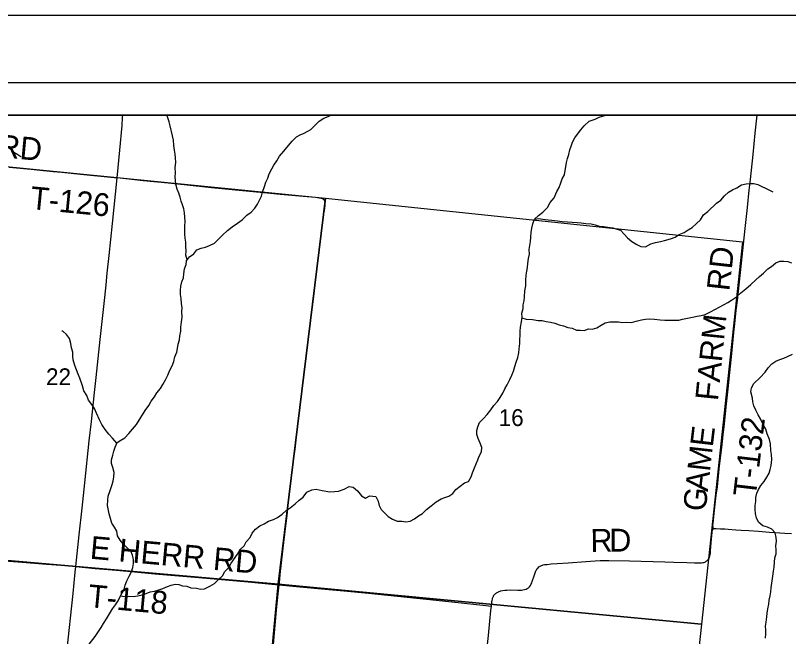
# Model space of a CAD drawing. Extents: x 0 to 1067, y 0 to 440.
# Drawn here: x 393.3 to 508.9, y 347.2 to 440 of the extents above; entities that cross this region are included whole.
import ezdxf

# ---------------------------------------------------------------- set-up
doc = ezdxf.new("R2010")
doc.units = 0
for name, color, linetype in [('GM_X_County_Road', 7, 'Continuous'), ('GM_X_County_Road_Text', 7, 'Continuous'), ('GM_X_Minor_River', 7, 'Continuous'), ('GM_X_Section', 7, 'Continuous'), ('GM_X_Section_Text', 7, 'Continuous'), ('GM_X_Township_Road', 7, 'Continuous'), ('GM_X_Township_Road_Text', 7, 'Continuous'), ('GM_X_US_Route', 7, 'Continuous'), ('SH_Border', 7, 'Continuous'), ('SH_Cut_Line', 7, 'Continuous'), ('SH_Text', 7, 'Continuous')]:
    doc.layers.add(name, color=color, linetype=linetype)

msp = doc.modelspace()

# ---------------------------------------------------------------- linework, layer by layer
at = {"layer": 'GM_X_County_Road'}
for points in [[(464.46, 351.72), (464.48, 351.95), (464.51, 352.18), (464.54, 352.41), (464.57, 352.57), (464.6, 352.73), (464.63, 352.88), (464.67, 353.01), (464.71, 353.09), (464.75, 353.17), (464.79, 353.24), (464.84, 353.33), (464.89, 353.4), (464.95, 353.47), (465.02, 353.54), (465.07, 353.59), (465.15, 353.65), (465.22, 353.7), (465.31, 353.76), (465.41, 353.81), (465.5, 353.86), (465.6, 353.9), (465.76, 353.96), (465.88, 353.99), (466.13, 354.05), (466.46, 354.09), (466.79, 354.11), (467.38, 354.12), (468.39, 354.11), (468.74, 354.11), (468.97, 354.11), (469.18, 354.13), (469.43, 354.18), (469.64, 354.25), (469.83, 354.33), (470.01, 354.45), (470.16, 354.6), (470.29, 354.79), (470.43, 355.03), (470.5, 355.19), (470.58, 355.38), (470.91, 356.38), (471.07, 356.83), (471.18, 357.06), (471.24, 357.2), (471.32, 357.31), (471.44, 357.45), (471.58, 357.58), (471.75, 357.69), (471.93, 357.78), (472.08, 357.84), (472.2, 357.87), (472.39, 357.91), (472.57, 357.93), (472.78, 357.95), (473.42, 358.01), (474.32, 358.07), (475.95, 358.19), (478.59, 358.38), (479.97, 358.48), (480.75, 358.52), (481.19, 358.53), (482.01, 358.53), (485.11, 358.47), (490.43, 358.35), (491.74, 358.3), (493.71, 358.23), (494.83, 358.18), (495.52, 358.16), (495.74, 358.16), (495.9, 358.18), (496.08, 358.21), (496.23, 358.23), (496.37, 358.27), (496.48, 358.32), (496.61, 358.41), (496.71, 358.49), (496.81, 358.59), (496.92, 358.73), (497.02, 358.88), (497.07, 359), (497.13, 359.17), (497.17, 359.36), (497.2, 359.5), (497.22, 359.62), (497.23, 359.79), (497.25, 359.96), (497.34, 361.24), (497.47, 362.74), (497.48, 362.85), (497.5, 362.96), (497.52, 363.03), (497.54, 363.09), (497.56, 363.13), (497.58, 363.17), (497.61, 363.21), (497.65, 363.24), (497.71, 363.27)], [(497.71, 363.27), (497.78, 363.3), (497.85, 363.31), (497.92, 363.31), (497.99, 363.31), (498.08, 363.31), (498.71, 363.28), (499.38, 363.25), (499.9, 363.21), (501.02, 363.12), (501.83, 363.06), (502.95, 362.99), (504.4, 362.89), (506.07, 362.78), (508.34, 362.62), (509.38, 362.55)], [(461.03, 321.28), (461.15, 321.95), (461.26, 322.66), (461.36, 323.36), (461.47, 324.28), (461.62, 325.62), (461.76, 326.9), (461.92, 328.34), (462.05, 329.49), (462.18, 330.74), (462.27, 331.57), (462.5, 333.82), (462.8, 336.66), (463.06, 338.89), (463.26, 340.5), (463.48, 342.36), (463.92, 346.42), (464.01, 347.3), (464.24, 349.44), (464.39, 351.07), (464.46, 351.72)]]:
    msp.add_lwpolyline(points, dxfattribs=at)
at = {"layer": 'GM_X_Minor_River'}
for points in [[(385.01, 424.77), (385.45, 424.18), (386.11, 424.09), (386.68, 424.08), (387.3, 423.64), (387.81, 422.96), (388.24, 422.39), (388.88, 421.86), (389.45, 421.6), (390.06, 421.26), (390.65, 420.96), (391.22, 420.72), (391.81, 420.49), (392.4, 420.14), (392.99, 419.55), (393.63, 419.2), (394.04, 418.93)], [(408.01, 371.69), (407.84, 372.45), (407.61, 373.02), (407.64, 373.59), (407.81, 374.27), (407.99, 374.88), (408.18, 375.47), (408.46, 376.18), (409.04, 376.52), (409.61, 376.87), (410.23, 377.51), (410.79, 378.16), (411.34, 378.86), (412.67, 380.97), (413.2, 381.72), (413.57, 382.37), (414.08, 383.01), (414.43, 383.6), (414.93, 384.25), (415.31, 384.86), (415.7, 385.52), (416.03, 386.25), (416.35, 386.99), (416.7, 387.65), (416.96, 388.29), (417.12, 388.95), (417.41, 389.65), (417.52, 390.24), (417.62, 390.88), (417.79, 391.53), (417.84, 392.13), (417.98, 392.81), (418.01, 393.4), (418.11, 394.22), (418.18, 394.9), (418.17, 395.74), (418.18, 396.31), (418.11, 396.97), (418.05, 397.7), (417.97, 398.29), (417.97, 398.93), (418.02, 399.54), (418.14, 400.2), (418.4, 400.79), (418.43, 401.36), (418.57, 402.11), (418.78, 402.76), (418.86, 403.33), (419.3, 403.92), (419.92, 404.37), (420.4, 404.98), (421.02, 405.24), (421.69, 405.37), (422.28, 405.62), (423.02, 405.97), (423.64, 406.54), (424.24, 407.15), (424.98, 407.87), (425.67, 408.4), (426.47, 408.94), (427.16, 409.46), (427.88, 410.13), (428.52, 410.6), (429.07, 411.19), (429.47, 411.78), (429.77, 412.39), (430.05, 412.98), (430.19, 413.57), (430.5, 414.43), (430.69, 415.08), (431.01, 415.69), (431.22, 416.35), (431.62, 417.07), (431.92, 417.64), (432.34, 418.29), (432.78, 418.99), (433.4, 419.71), (434.1, 420.55), (434.67, 421.2), (435.3, 421.85), (435.87, 422.14), (436.47, 422.41), (437.45, 422.97), (438.12, 423.67), (438.7, 424.21), (439.41, 424.63), (440.03, 424.92), (440.46, 425.11)], [(418.95, 403.45), (418.73, 404.17), (418.78, 404.79), (418.76, 405.52), (418.72, 406.13), (418.66, 406.7), (418.6, 407.31), (418.6, 407.9), (418.59, 408.49), (418.64, 409.18), (418.58, 409.86), (418.54, 410.49), (418.47, 411.09), (418.27, 411.68), (418.07, 412.25), (417.9, 412.84), (417.7, 413.46), (417.45, 414.03), (417.27, 414.8), (417.13, 415.87), (417.2, 416.48), (417.14, 417.28), (417.26, 418), (417.2, 418.71), (417.13, 419.28), (417.07, 419.89), (416.96, 420.57), (416.88, 421.37), (416.73, 422.03), (416.4, 423.51), (416.27, 424.12), (416.07, 424.71), (415.91, 425.11)], [(464.36, 381.06), (464.8, 381.69), (465.38, 382.3), (465.75, 382.87), (466.17, 383.53), (466.45, 384.21), (466.84, 384.77), (467.24, 385.59), (467.54, 386.25), (467.75, 386.81), (467.96, 387.52), (468.18, 388.18), (468.39, 388.86), (468.55, 389.56), (468.63, 390.15), (468.7, 390.97), (468.71, 391.54), (468.76, 392.15), (468.77, 392.79), (468.79, 393.41), (468.94, 394.2), (469.04, 394.88), (469.02, 395.5), (469.23, 396.18), (469.21, 396.77), (469.36, 397.36), (469.41, 397.95), (469.44, 398.84), (469.61, 399.59), (469.59, 400.36), (469.64, 401.2), (469.76, 401.77), (469.86, 402.34), (469.91, 402.91), (469.99, 403.68), (470.15, 404.34), (470.09, 405), (470.19, 405.61), (470.33, 406.22), (470.36, 406.84), (470.39, 407.56), (470.51, 408.22), (470.67, 408.86), (470.91, 409.54), (471.53, 410.12), (472.13, 410.62), (472.87, 411.29), (473.26, 412.02), (473.84, 412.72), (474.24, 413.71), (474.59, 414.28), (474.84, 414.96), (475.06, 415.59), (475.4, 416.2), (475.48, 416.82), (475.57, 417.38), (475.69, 418.02), (475.86, 418.61), (476.05, 419.22), (476.19, 419.9), (476.38, 420.47), (476.57, 421.06), (476.96, 421.71), (477.33, 422.28), (477.82, 422.91), (478.35, 423.52), (479.07, 424.19), (479.96, 424.5), (480.56, 424.79), (481.6, 425.11)], [(470.94, 409.57), (471.57, 409.65), (472.17, 409.57), (472.94, 409.47), (473.51, 409.38), (474.33, 409.28), (475.06, 409.22), (475.84, 409.17), (476.53, 409.1), (477.28, 409.04), (477.89, 409.02), (478.58, 408.92), (479.36, 408.86), (479.97, 408.68), (480.56, 408.53), (481.25, 408.44), (481.89, 408.34), (482.62, 408.26), (483.21, 408.08), (483.78, 407.91), (484.3, 407.32), (484.84, 406.74), (485.45, 406.21), (486.2, 405.75), (486.82, 405.47), (487.52, 405.4), (488.31, 405.84), (489.02, 406.04), (489.75, 406.22), (490.34, 406.35), (491.24, 406.61), (491.97, 406.88), (492.54, 407.28), (493.28, 407.57), (493.88, 407.97), (494.5, 408.31), (495.16, 408.92), (495.74, 409.43), (496.2, 410.18), (496.83, 410.7), (498.12, 411.96), (498.76, 412.38), (499.31, 413.02), (499.94, 413.6), (500.53, 413.94), (501.18, 414.23), (501.89, 414.7), (502.58, 414.85), (503.15, 414.87), (503.74, 414.88), (504.31, 414.72), (504.9, 414.44), (505.47, 414.21), (506.08, 413.88), (506.54, 413.65)], [(469.02, 394.79), (469.65, 394.58), (470.59, 394.53), (471.48, 394.38), (472.07, 394.4), (472.66, 394.23), (473.28, 394.14), (473.94, 393.99), (474.58, 393.78), (475.24, 393.59), (475.88, 393.36), (476.54, 393.28), (477.17, 392.98), (477.75, 392.98), (478.36, 392.92), (478.98, 393.15), (479.55, 393.09), (480.22, 393.29), (480.86, 393.72), (481.48, 394.05), (482.17, 394.21), (482.83, 394.22), (483.49, 394.22), (484.06, 394.12), (484.7, 394.16), (485.41, 394.11), (486.12, 394.28), (486.92, 394.48), (487.49, 394.61), (488.11, 394.65), (488.86, 394.6), (489.71, 394.5), (490.42, 394.44), (491.76, 394.43), (492.49, 394.45), (493.07, 394.58), (493.8, 394.77), (494.55, 394.88), (495.22, 395.03), (495.84, 395.14), (496.43, 395.32), (497.26, 395.72), (497.97, 396.12), (498.54, 396.41), (499.26, 396.81), (499.83, 397.11), (500.4, 397.42), (501.12, 397.96), (501.78, 398.54), (502.52, 399.15), (503.26, 399.78), (503.99, 400.43), (504.59, 400.97), (505.17, 401.47), (505.79, 402.12), (506.37, 402.46), (507.01, 403), (507.61, 403.29), (508.22, 403.26), (508.79, 403.23), (509.36, 403)], [(408.43, 376.09), (407.78, 376.8), (407.24, 377.42), (406.7, 378.13), (406.18, 378.87), (405.84, 379.55), (405.37, 380.56), (405.06, 381.27), (404.7, 381.84), (404.2, 382.51), (403.94, 383.2), (403.49, 383.91), (403.31, 384.66), (402.89, 385.78), (402.66, 386.37), (402.37, 387.04), (402.15, 387.68), (401.88, 388.5), (401.84, 389.09), (401.85, 389.68), (401.65, 390.34), (401.54, 390.96), (401.34, 391.69), (400.91, 392.29), (400.32, 392.79), (400.21, 392.82)], [(505.88, 387.32), (506.41, 387.93), (507.01, 388.31), (507.63, 388.56), (508.2, 388.76), (508.78, 389.02), (509.51, 389.38)], [(505.47, 346.94), (505.54, 347.55), (505.53, 348.12), (505.46, 348.7), (505.56, 349.33), (505.66, 350.09), (505.71, 350.66), (505.81, 351.29), (505.95, 352), (506.02, 352.59), (506.14, 353.23), (506.24, 353.85), (506.31, 354.46), (506.41, 355.14), (506.54, 356.19), (506.66, 356.92), (506.75, 357.54), (506.81, 358.27), (506.88, 358.93), (507.07, 359.54), (507.05, 360.14), (506.99, 360.73), (507.09, 361.41), (507.05, 361.98), (506.89, 362.65), (506.39, 363.22), (505.78, 363.5), (505.07, 363.71), (504.48, 364.2), (504.1, 364.84), (503.97, 365.53), (503.91, 366.14), (503.94, 366.74), (504.01, 367.33), (504.04, 367.97), (504.18, 368.58), (504.44, 369.15), (504.76, 369.74), (505.25, 370.35), (505.69, 371.01), (505.99, 371.57), (506.18, 372.14), (506.32, 372.71), (506.42, 373.64), (506.38, 374.35), (506.25, 374.99), (506.21, 375.97), (506.08, 376.61), (505.72, 377.48), (505.53, 378.17), (505.17, 378.78), (504.74, 379.72), (504.38, 380.3), (504.02, 380.98), (503.73, 381.65), (503.55, 382.24), (503.51, 382.81), (503.29, 383.75), (503.37, 384.34), (503.71, 384.97), (504.66, 385.88), (505.44, 386.69), (505.88, 387.32)], [(408.94, 353.23), (409.6, 353.17), (410.22, 353.21), (410.88, 353.16), (411.57, 353.24), (412.19, 353.42), (412.8, 353.62), (413.42, 353.84), (414.04, 353.95), (414.73, 354.13), (415.32, 354.35), (415.99, 354.64), (416.56, 354.82), (417.13, 354.97), (417.71, 354.94), (418.27, 354.73), (418.87, 354.68), (419.51, 354.45), (420.33, 354.37), (420.92, 354.23), (421.56, 354.27), (422.34, 354.69), (423.03, 355.07), (423.63, 355.71), (424.23, 356.25), (424.58, 356.86), (425.15, 357.45), (425.55, 358.13), (426.47, 359.49), (426.89, 360.17), (427.49, 360.74), (427.77, 361.33), (428.35, 361.98), (428.69, 362.6), (429.18, 363.21), (429.8, 363.7), (430.44, 364.02), (431.11, 364.4), (431.87, 364.64), (432.48, 364.96), (433.17, 365.45), (433.77, 365.99), (434.35, 366.38), (435.11, 366.98), (435.71, 367.53), (436.3, 368.02), (436.86, 368.75), (437.59, 369.1), (438.26, 369.21), (439.15, 369), (440.29, 368.78), (440.97, 368.82), (441.57, 368.88), (442.44, 369.17), (443.2, 369.6), (443.77, 369.5), (444.45, 368.92), (445.01, 368.19), (445.62, 367.86), (446.27, 368.18), (447.18, 368.08), (447.54, 367.39), (447.65, 366.77), (447.98, 366.15), (449.03, 365.12), (449.64, 364.7), (450.34, 364.42), (451.05, 364.39), (451.67, 364.31), (452.31, 364.4), (452.97, 364.78), (453.55, 365.21), (454.17, 365.54), (454.77, 366.15), (455.46, 366.72), (456.22, 367.3), (456.93, 367.73), (457.5, 367.95), (458.1, 368.13), (458.67, 368.53), (459.16, 369.12), (459.78, 369.64), (460.45, 370.16), (461.04, 370.36), (461.42, 371.02), (461.65, 371.63), (461.91, 372.4), (462.19, 372.97), (462.42, 373.56), (462.65, 374.13), (462.98, 374.78), (463.01, 375.4), (462.76, 376.06), (462.47, 376.77), (462.3, 377.34), (462.26, 377.94), (462.42, 378.53), (462.68, 379.16), (463.3, 379.75), (463.83, 380.36), (464.36, 381.06)], [(404.26, 346), (405.19, 347.18), (405.67, 347.93), (406.07, 348.52), (406.44, 349.11), (406.88, 349.79), (407.32, 350.56), (407.76, 351.29), (408.2, 351.88), (408.61, 352.49), (408.85, 353.06), (409.2, 353.68), (409.5, 354.24), (409.66, 354.84), (409.9, 355.5), (410.27, 356.2), (410.62, 356.81), (410.83, 357.5), (410.93, 358.09), (410.91, 358.68), (410.75, 359.32), (410.53, 359.92), (409.94, 360.47), (409.35, 361), (408.92, 361.58), (408.5, 362.24), (408.41, 362.9), (408.07, 363.52), (407.67, 364.1), (407.49, 364.81), (407.29, 365.49), (407.03, 366.77), (407.06, 367.53), (407.13, 368.16), (407.42, 369.01), (407.67, 369.73), (407.89, 370.39), (407.98, 371.03), (408.01, 371.69)]]:
    msp.add_lwpolyline(points, dxfattribs=at)
at = {"layer": 'GM_X_Section'}
for points in [[(377.26, 418.88), (439.65, 412.67), (432.58, 354.98), (371.52, 360.33)], [(502.03, 406.17), (495.9, 348.99), (432.58, 354.98), (439.65, 412.67)], [(432.58, 354.98), (426.84, 293.81), (365.53, 299.9), (371.52, 360.33)], [(432.58, 354.98), (495.9, 348.99), (489.23, 287.4), (426.84, 293.81)]]:
    msp.add_lwpolyline(points, close=True, dxfattribs=at)
at = {"layer": 'GM_X_Township_Road'}
for points in [[(539, 425.11), (252.4, 425.11), (247.73, 377.87), (241.1, 310.88), (230.69, 191.54)], [(497.71, 363.27), (497.68, 363.33), (497.65, 363.41), (497.62, 363.49), (497.62, 363.55), (497.61, 363.62), (497.61, 363.82), (497.63, 364.08), (497.8, 365.59), (498.11, 368.29), (498.26, 369.55), (498.55, 372.22), (498.91, 375.4), (499.14, 377.33), (499.31, 378.96), (499.58, 381.52), (499.91, 384.63), (500.11, 386.61), (500.41, 389.46), (500.75, 392.6), (500.88, 393.93), (501.1, 395.97), (501.26, 397.38), (501.87, 402.97), (502.18, 405.83), (502.43, 408.16), (502.76, 411.31), (503.03, 413.91), (503.21, 415.5), (503.61, 419.21), (503.94, 422.4), (504.24, 425.11)], [(408.48, 415.71), (408, 415.75), (402.99, 416.25), (400.17, 416.52), (398.91, 416.65), (395.56, 416.96), (392.33, 417.26)], [(432.71, 354.9), (432.74, 355.19), (432.86, 356.42), (433, 357.75), (433.32, 360.38), (433.57, 362.49), (433.88, 365.27), (434.06, 366.79), (434.36, 369.49), (434.77, 372.78), (435.08, 375.19), (435.47, 378.33), (435.8, 381.07), (436.06, 383.18), (436.35, 385.55), (436.51, 386.8), (436.66, 388.14), (436.9, 390.27), (437.05, 391.58), (437.32, 393.55), (437.49, 394.91), (437.89, 397.98), (438.1, 399.67), (438.36, 401.92), (438.56, 403.59), (438.74, 404.99), (438.95, 406.63), (439.14, 408.5), (439.24, 409.29), (439.35, 410.06), (439.52, 411.14), (439.59, 411.68), (439.6, 411.8), (439.61, 411.89), (439.61, 411.97), (439.6, 412.04), (439.6, 412.11), (439.58, 412.17), (439.56, 412.21), (439.54, 412.26), (439.5, 412.32), (439.46, 412.37), (439.42, 412.43), (439.38, 412.47), (439.32, 412.51), (439.27, 412.55), (439.2, 412.59), (439.12, 412.62), (439.05, 412.65), (438.95, 412.68), (438.86, 412.7), (438.75, 412.71), (438.65, 412.73), (438.45, 412.75), (438.14, 412.77), (436.29, 412.92), (435.14, 413.03), (432.84, 413.24), (431.39, 413.38), (427.24, 413.8), (422.6, 414.26), (418.48, 414.67), (416.11, 414.91), (412.37, 415.3), (408.48, 415.71)], [(340.07, 362.89), (342.03, 362.73), (343.55, 362.6), (345.67, 362.43), (348.42, 362.2), (350.35, 362.03), (352.28, 361.87), (353.73, 361.75), (355.22, 361.62), (357.59, 361.43), (360.79, 361.15), (364.17, 360.86), (368.85, 360.46), (373.41, 360.07), (377.23, 359.73), (382.76, 359.25), (390.19, 358.6), (394.27, 358.26), (397.88, 357.98), (400.11, 357.81), (401.81, 357.67), (402.3, 357.63)], [(402.3, 357.63), (405.19, 357.35), (407.13, 357.16), (407.16, 357.16), (410.59, 356.86), (414.13, 356.55), (420.67, 355.97), (428.09, 355.32), (431.62, 355.01), (432.71, 354.9)], [(431.87, 345.99), (432.13, 348.85), (432.38, 351.63), (432.56, 353.53), (432.71, 354.9)], [(432.71, 354.9), (435.81, 354.61), (439.6, 354.24), (442.38, 353.98), (446.06, 353.63), (454.75, 352.74), (457.16, 352.49), (463.19, 351.85), (464.46, 351.72)]]:
    msp.add_lwpolyline(points, dxfattribs=at)
at = {"layer": 'GM_X_US_Route'}
msp.add_lwpolyline([(400.94, 344.83), (401.87, 353.58), (402.21, 356.77), (402.3, 357.63), (402.8, 362.39), (403.23, 366.37), (403.63, 370.15), (404.3, 376.42), (404.62, 379.31), (405.08, 383.64), (405.32, 385.9), (405.93, 391.57), (406.61, 397.84), (406.81, 399.73), (406.99, 401.47), (407.28, 404.14), (407.78, 408.89), (408.48, 415.71), (408.88, 419.85), (409.21, 423.54), (409.29, 424.77), (409.32, 425.11)], dxfattribs=at)
at = {"layer": 'SH_Border'}
msp.add_lwpolyline([(30, 430), (670, 430), (670, 10), (30, 10)], close=True, dxfattribs=at)
at = {"layer": 'SH_Cut_Line'}
msp.add_lwpolyline([(0, 0), (680, 0), (680, 440), (0, 440)], close=True, dxfattribs=at)
at = {"layer": 'SH_Text'}
msp.add_lwpolyline([(131, 425.11), (539, 425.11), (539, 17.11), (131, 17.11)], close=True, dxfattribs=at)

# ---------------------------------------------------------------- texts
at = {"layer": 'GM_X_County_Road_Text'}
for s, rotation, p in [('R', 1.0031, (479.31, 359.81)), ('D', 0.0474, (482.1, 359.86))]:
    msp.add_text(s, height=3.41, rotation=rotation, dxfattribs=at).set_placement(p)
at = {"layer": 'GM_X_Section_Text'}
for s, p in [('22', (397.83, 384.74)), ('16', (465.55, 378.63))]:
    msp.add_text(s, height=2.511, rotation=0, dxfattribs=at).set_placement(p)
at = {"layer": 'GM_X_Township_Road_Text'}
for s, height, rotation, p in [('RD', 3.409, 354.5823, (390.51, 418.86)), ('T-126', 3.409, 354.4276, (395.35, 411.08)), ('RD', 3.409, 83.6054, (500.05, 398.72)), ('FARM', 3.409, 84.1976, (498.34, 382.31)), ('T-132', 3.409, 83.2931, (504.01, 367.94)), ('E', 3.41, 83.2476, (497.57, 375.4)), ('M', 3.41, 83.6546, (497.16, 371.73)), ('A', 3.41, 83.6594, (496.83, 368.75)), ('G', 3.41, 83.6594, (496.5, 365.77)), ('E HERR RD', 3.409, 354.8178, (404.31, 358.81)), ('T-118', 3.409, 354.6819, (404.02, 351.58))]:
    msp.add_text(s, height=height, rotation=rotation, dxfattribs=at).set_placement(p)

doc.saveas('drawing.dxf')
